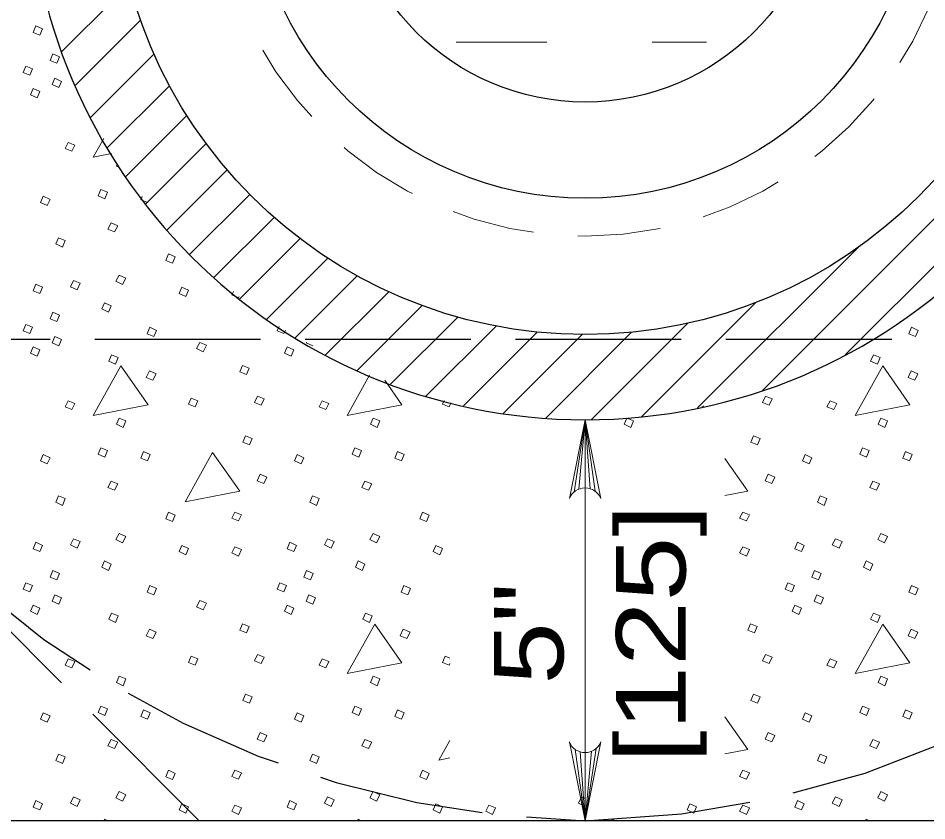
# Model space of a CAD drawing. Extents: x 1036.7 to 1070.7, y 883.9 to 905.9.
# Drawn here: x 1046.559 to 1048.598, y 887.577 to 889.378 of the extents above; entities that cross this region are included whole.
import ezdxf
from ezdxf.enums import TextEntityAlignment as Align

# ---------------------------------------------------------------- set-up
doc = ezdxf.new("R2010")
doc.units = 0
doc.header["$LTSCALE"] = 0.062
doc.linetypes.add('LONG_DASHED', pattern=[7.5, 6, -1.5])
doc.linetypes.add('MEDIUM_DASHED', pattern=[4.5, 3, -1.5])
doc.layers.add('1', color=7, linetype='Continuous', lineweight=13)

msp = doc.modelspace()

# ---------------------------------------------------------------- linework, layer by layer
at = {"layer": '1'}
for p, q in [((1046.65633, 889.30225), (1046.80892, 889.45483)), ((1046.68667, 889.22658), (1046.83392, 889.37383)), ((1047.542, 889.32425), (1047.74533, 889.32425)), ((1047.98175, 889.32425), (1048.10333, 889.32425)), ((1048.22892, 888.5425), (1049.01425, 889.32775)), ((1046.72092, 889.15475), (1046.864, 889.29783)), ((1046.75892, 889.08675), (1046.89883, 889.22658)), ((1046.80025, 889.02208), (1046.93783, 889.15958)), ((1048.41458, 888.62217), (1048.93458, 889.14208)), ((1046.84492, 888.96075), (1046.98092, 889.09675)), ((1046.89283, 888.90267), (1047.02792, 889.03775)), ((1046.94383, 888.84767), (1047.07875, 888.9825)), ((1046.998, 888.79583), (1047.13325, 888.93108)), ((1047.05533, 888.74708), (1047.19158, 888.88333)), ((1048.08367, 888.50333), (1048.44467, 888.86417)), ((1047.11625, 888.70208), (1047.25383, 888.83958)), ((1047.18058, 888.66033), (1047.32, 888.79983)), ((1047.24825, 888.622), (1047.3905, 888.76425)), ((1047.3195, 888.58725), (1047.46558, 888.73325)), ((1047.958, 888.48358), (1048.21417, 888.73983)), ((1047.39467, 888.55642), (1047.54558, 888.70733)), ((1047.474, 888.52975), (1047.63142, 888.68708)), ((1047.84558, 888.47733), (1048.06175, 888.69342)), ((1047.55808, 888.50783), (1047.72383, 888.6735)), ((1047.64742, 888.49117), (1047.82433, 888.668)), ((1047.74292, 888.48067), (1047.9355, 888.67317)), ((1047.80642, 888.31467), (1047.83117, 888.47683)), ((1047.81683, 888.32083), (1047.83117, 888.47683)), ((1047.83117, 888.47683), (1047.83117, 887.88908)), ((1047.83117, 888.32367), (1047.83117, 888.47683)), ((1047.8425, 888.322), (1047.83117, 888.47683)), ((1047.85358, 888.31658), (1047.83117, 888.47683)), ((1047.51725, 887.94592), (1047.528, 887.94167)), ((1047.83117, 887.57667), (1047.83117, 887.88908)), ((1047.80875, 887.73692), (1047.83117, 887.57667)), ((1047.81983, 887.7315), (1047.83117, 887.57667)), ((1047.856, 887.73883), (1047.83117, 887.57667)), ((1047.84558, 887.73267), (1047.83117, 887.57667)), ((1047.83117, 887.72983), (1047.83117, 887.57667)), ((1047.82308, 887.63017), (1047.83117, 887.62692)), ((1046.75117, 887.57667), (1046.75267, 887.58017)), ((1046.75267, 887.58017), (1046.76008, 887.57667)), ((1047.32083, 887.57667), (1047.32233, 887.58017)), ((1047.32233, 887.58017), (1047.32983, 887.57667)), ((1047.89058, 887.57667), (1047.89208, 887.58017)), ((1047.89208, 887.58017), (1047.89958, 887.57667)), ((1048.46033, 887.57667), (1048.46183, 887.58017)), ((1048.46183, 887.58017), (1048.46933, 887.57667))]:
    msp.add_line(p, q, dxfattribs=at)
at = {"layer": '1', "linetype": 'LONG_DASHED', "lineweight": 25}
for p, q in [((1045.72733, 888.81858), (1046.9655, 887.57667)), ((1049.935, 888.65658), (1046.35942, 888.65658))]:
    msp.add_line(p, q, dxfattribs=at)
at = {"layer": '1', "lineweight": 25}
for points in [[(1045.72733, 891.87417), (1049.935, 891.87417), (1049.935, 887.57667), (1047.83117, 887.57667)], [(1047.83117, 887.57667), (1045.72733, 887.57667), (1045.72733, 891.87417)]]:
    msp.add_lwpolyline(points, dxfattribs=at)
at = {"layer": '1'}
for points in [[(1046.59867, 889.36117), (1046.61367, 889.35417), (1046.60767, 889.34017), (1046.59267, 889.34617)], [(1046.63667, 889.29817), (1046.65167, 889.29117), (1046.64567, 889.27717), (1046.63067, 889.28317)], [(1046.57675, 889.27017), (1046.59167, 889.26417), (1046.58567, 889.25017), (1046.57075, 889.25617)], [(1046.64167, 889.24317), (1046.65667, 889.23625), (1046.65067, 889.22225), (1046.63567, 889.22925)], [(1046.59267, 889.22025), (1046.60767, 889.21325), (1046.60167, 889.19925), (1046.58667, 889.20625)], [(1046.67167, 889.09925), (1046.68667, 889.09325), (1046.67967, 889.07933), (1046.66467, 889.08533)], [(1046.74467, 888.99333), (1046.75958, 888.98733), (1046.75367, 888.97233), (1046.73867, 888.97933)], [(1046.61567, 888.97833), (1046.63067, 888.97133), (1046.62467, 888.95733), (1046.60967, 888.96433)], [(1046.76758, 888.91842), (1046.78258, 888.91242), (1046.77558, 888.89842), (1046.76058, 888.90442)], [(1046.64967, 888.88542), (1046.66467, 888.87942), (1046.65867, 888.86442), (1046.64367, 888.87142)], [(1046.89658, 888.84942), (1046.91158, 888.84242), (1046.90558, 888.82842), (1046.89058, 888.83442)], [(1046.68367, 888.7895), (1046.69867, 888.7835), (1046.69167, 888.7685), (1046.67667, 888.7755)], [(1046.78558, 888.80142), (1046.80058, 888.7945), (1046.79358, 888.7805), (1046.77858, 888.7875)], [(1046.59867, 888.7815), (1046.61367, 888.7745), (1046.60767, 888.7605), (1046.59267, 888.7665)], [(1046.92658, 888.7745), (1046.9415, 888.7675), (1046.93558, 888.7535), (1046.92058, 888.7605)], [(1046.75267, 888.7395), (1046.76758, 888.7325), (1046.76158, 888.7185), (1046.74667, 888.7255)], [(1046.63667, 888.7185), (1046.65167, 888.7115), (1046.64567, 888.6975), (1046.63067, 888.7035)], [(1046.57675, 888.6905), (1046.59167, 888.6845), (1046.58567, 888.6705), (1046.57075, 888.6765)], [(1046.85458, 888.6845), (1046.86958, 888.6775), (1046.86358, 888.6635), (1046.84858, 888.6695)], [(1048.56375, 888.6845), (1048.57875, 888.6775), (1048.57275, 888.6635), (1048.55775, 888.6695)], [(1046.64167, 888.6635), (1046.65667, 888.65658), (1046.65067, 888.64258), (1046.63567, 888.64958)], [(1046.59267, 888.64058), (1046.60767, 888.63358), (1046.60167, 888.61958), (1046.58667, 888.62658)], [(1046.9665, 888.65058), (1046.9815, 888.64458), (1046.9745, 888.62958), (1046.9595, 888.63658)], [(1047.16242, 888.64058), (1047.17742, 888.63358), (1047.17142, 888.61958), (1047.15642, 888.62658)], [(1046.76858, 888.62258), (1046.78358, 888.61658), (1046.77758, 888.60158), (1046.76258, 888.60858)], [(1048.47783, 888.62258), (1048.49283, 888.61658), (1048.48683, 888.60158), (1048.47183, 888.60858)], [(1046.78958, 888.59758), (1046.72767, 888.48667), (1046.85058, 888.51067)], [(1046.85358, 888.58658), (1046.86858, 888.57958), (1046.86158, 888.56558), (1046.84658, 888.57158)], [(1047.0625, 888.59858), (1047.0775, 888.59258), (1047.0715, 888.57858), (1047.0565, 888.58458)], [(1048.49883, 888.59758), (1048.43683, 888.48667), (1048.55975, 888.51067)], [(1048.56275, 888.58658), (1048.57775, 888.57958), (1048.57075, 888.56558), (1048.55575, 888.57158)], [(1046.67167, 888.51958), (1046.68667, 888.51358), (1046.67967, 888.49967), (1046.66467, 888.50567)], [(1046.9475, 888.52558), (1046.9625, 888.51958), (1046.9565, 888.50567), (1046.9415, 888.51167)], [(1047.0965, 888.52958), (1047.1115, 888.52358), (1047.1045, 888.50967), (1047.0895, 888.51558)], [(1047.24142, 888.51958), (1047.25642, 888.51358), (1047.24942, 888.49967), (1047.23442, 888.50567)], [(1048.23592, 888.52958), (1048.25092, 888.52358), (1048.24392, 888.50967), (1048.22892, 888.51558)], [(1048.38083, 888.51958), (1048.39583, 888.51358), (1048.38883, 888.49967), (1048.37383, 888.50567)], [(1046.78558, 888.48067), (1046.80058, 888.47467), (1046.79458, 888.45967), (1046.77958, 888.46667)], [(1047.35533, 888.48067), (1047.37033, 888.47467), (1047.36433, 888.45967), (1047.34933, 888.46667)], [(1047.92508, 888.48067), (1047.94008, 888.47467), (1047.93408, 888.45967), (1047.91908, 888.46667)], [(1048.49483, 888.48067), (1048.50983, 888.47467), (1048.50383, 888.45967), (1048.48883, 888.46667)], [(1047.0695, 888.44067), (1047.0845, 888.43467), (1047.0785, 888.42067), (1047.0635, 888.42667)], [(1048.20892, 888.44067), (1048.22392, 888.43467), (1048.21792, 888.42067), (1048.20292, 888.42667)], [(1046.61567, 888.39867), (1046.63067, 888.39167), (1046.62467, 888.37767), (1046.60967, 888.38467)], [(1046.74467, 888.41367), (1046.75958, 888.40767), (1046.75367, 888.39267), (1046.73867, 888.39967)], [(1046.84058, 888.40567), (1046.85558, 888.39867), (1046.84958, 888.38467), (1046.83458, 888.39067)], [(1046.9955, 888.40367), (1046.93358, 888.29275), (1047.0565, 888.31675)], [(1047.18542, 888.39867), (1047.20042, 888.39167), (1047.19442, 888.37767), (1047.17942, 888.38467)], [(1047.31433, 888.41367), (1047.32933, 888.40767), (1047.32333, 888.39267), (1047.30833, 888.39967)], [(1047.41033, 888.40567), (1047.42533, 888.39867), (1047.41933, 888.38467), (1047.40433, 888.39067)], [(1048.32492, 888.39867), (1048.33992, 888.39167), (1048.33392, 888.37767), (1048.31892, 888.38467)], [(1048.45383, 888.41367), (1048.46883, 888.40767), (1048.46283, 888.39267), (1048.44783, 888.39967)], [(1048.54975, 888.40567), (1048.56475, 888.39867), (1048.55875, 888.38467), (1048.54375, 888.39067)], [(1047.1025, 888.35475), (1047.11742, 888.34775), (1047.11042, 888.33375), (1047.0955, 888.33975)], [(1048.24192, 888.35475), (1048.25692, 888.34775), (1048.24992, 888.33375), (1048.23492, 888.33975)], [(1046.76758, 888.33875), (1046.78258, 888.33275), (1046.77558, 888.31875), (1046.76058, 888.32475)], [(1047.33733, 888.33875), (1047.35233, 888.33275), (1047.34533, 888.31875), (1047.33033, 888.32475)], [(1048.47683, 888.33875), (1048.49183, 888.33275), (1048.48483, 888.31875), (1048.46983, 888.32475)], [(1046.64967, 888.30575), (1046.66467, 888.29975), (1046.65867, 888.28475), (1046.64367, 888.29175)], [(1047.21942, 888.30575), (1047.23442, 888.29975), (1047.22842, 888.28475), (1047.21342, 888.29175)], [(1048.35883, 888.30575), (1048.37383, 888.29975), (1048.36783, 888.28475), (1048.35292, 888.29175)], [(1046.89658, 888.26975), (1046.91158, 888.26275), (1046.90558, 888.24875), (1046.89058, 888.25475)], [(1047.0455, 888.26975), (1047.0605, 888.26375), (1047.0535, 888.24975), (1047.0385, 888.25575)], [(1047.46625, 888.26975), (1047.48125, 888.26275), (1047.47525, 888.24875), (1047.46033, 888.25475)], [(1048.18492, 888.26975), (1048.19992, 888.26375), (1048.19292, 888.24975), (1048.17792, 888.25575)], [(1046.78558, 888.22175), (1046.80058, 888.21483), (1046.79358, 888.20083), (1046.77858, 888.20783)], [(1047.35533, 888.22175), (1047.37033, 888.21483), (1047.36333, 888.20083), (1047.34833, 888.20783)], [(1048.49483, 888.22175), (1048.50983, 888.21483), (1048.50283, 888.20083), (1048.48783, 888.20783)], [(1046.59867, 888.20183), (1046.61367, 888.19483), (1046.60767, 888.18083), (1046.59267, 888.18683)], [(1046.68367, 888.20983), (1046.69867, 888.20383), (1046.69167, 888.18883), (1046.67667, 888.19583)], [(1046.92658, 888.19483), (1046.9415, 888.18783), (1046.93558, 888.17383), (1046.92058, 888.18083)], [(1047.0455, 888.19183), (1047.0605, 888.18583), (1047.0535, 888.17083), (1047.0385, 888.17783)], [(1047.16842, 888.20183), (1047.18342, 888.19483), (1047.17742, 888.18083), (1047.16242, 888.18683)], [(1047.25342, 888.20983), (1047.26842, 888.20383), (1047.26142, 888.18883), (1047.24642, 888.19583)], [(1047.49625, 888.19483), (1047.51125, 888.18783), (1047.50525, 888.17383), (1047.49025, 888.18083)], [(1048.18492, 888.19183), (1048.19992, 888.18583), (1048.19292, 888.17083), (1048.17792, 888.17783)], [(1048.30792, 888.20183), (1048.32292, 888.19483), (1048.31692, 888.18083), (1048.30192, 888.18683)], [(1048.39283, 888.20983), (1048.40783, 888.20383), (1048.40083, 888.18883), (1048.38583, 888.19583)], [(1046.75267, 888.15983), (1046.76758, 888.15283), (1046.76158, 888.13883), (1046.74667, 888.14583)], [(1047.32233, 888.15983), (1047.33733, 888.15283), (1047.33133, 888.13883), (1047.31633, 888.14583)], [(1048.46183, 888.15983), (1048.47683, 888.15283), (1048.47083, 888.13883), (1048.45583, 888.14583)], [(1046.63667, 888.13883), (1046.65167, 888.13183), (1046.64567, 888.11783), (1046.63067, 888.12383)], [(1047.20642, 888.13883), (1047.22142, 888.13183), (1047.21542, 888.11783), (1047.20042, 888.12383)], [(1048.34592, 888.13883), (1048.36083, 888.13183), (1048.35483, 888.11783), (1048.33992, 888.12383)], [(1046.57675, 888.11083), (1046.59167, 888.10483), (1046.58567, 888.09083), (1046.57075, 888.09683)], [(1047.14642, 888.11083), (1047.16142, 888.10483), (1047.15542, 888.09083), (1047.14042, 888.09683)], [(1048.28592, 888.11083), (1048.30092, 888.10483), (1048.29492, 888.09083), (1048.27992, 888.09683)], [(1046.85458, 888.10483), (1046.86958, 888.09783), (1046.86358, 888.08383), (1046.84858, 888.08983)], [(1047.42433, 888.10483), (1047.43933, 888.09783), (1047.43333, 888.08383), (1047.41833, 888.08983)], [(1048.56375, 888.10483), (1048.57875, 888.09783), (1048.57275, 888.08383), (1048.55775, 888.08983)], [(1046.64167, 888.08383), (1046.65667, 888.07683), (1046.65067, 888.06292), (1046.63567, 888.06992)], [(1046.9665, 888.07092), (1046.9815, 888.06492), (1046.9745, 888.04992), (1046.9595, 888.05692)], [(1047.21142, 888.08383), (1047.22642, 888.07683), (1047.22042, 888.06292), (1047.20542, 888.06992)], [(1048.35083, 888.08383), (1048.36583, 888.07683), (1048.35983, 888.06292), (1048.34492, 888.06992)], [(1046.59267, 888.06092), (1046.60767, 888.05392), (1046.60167, 888.03992), (1046.58667, 888.04692)], [(1047.16242, 888.06092), (1047.17742, 888.05392), (1047.17142, 888.03992), (1047.15642, 888.04692)], [(1048.30192, 888.06092), (1048.31692, 888.05392), (1048.31092, 888.03992), (1048.29592, 888.04692)], [(1046.76858, 888.04292), (1046.78358, 888.03692), (1046.77758, 888.02192), (1046.76258, 888.02892)], [(1047.33833, 888.04292), (1047.35333, 888.03692), (1047.34733, 888.02192), (1047.33233, 888.02892)], [(1048.47783, 888.04292), (1048.49283, 888.03692), (1048.48683, 888.02192), (1048.47183, 888.02892)], [(1047.0625, 888.01892), (1047.0775, 888.01292), (1047.0715, 887.99892), (1047.0565, 888.00492)], [(1047.35933, 888.01792), (1047.29733, 887.907), (1047.42033, 887.931)], [(1048.20192, 888.01892), (1048.21692, 888.01292), (1048.21092, 887.99892), (1048.19592, 888.00492)], [(1048.49883, 888.01792), (1048.43683, 887.907), (1048.55975, 887.931)], [(1046.85358, 888.00692), (1046.86858, 887.99992), (1046.86158, 887.98592), (1046.84658, 887.99192)], [(1047.42333, 888.00692), (1047.43833, 887.99992), (1047.43133, 887.98592), (1047.41633, 887.99192)], [(1048.56275, 888.00692), (1048.57775, 887.99992), (1048.57075, 887.98592), (1048.55575, 887.99192)], [(1047.0965, 887.94992), (1047.1115, 887.94392), (1047.1045, 887.93), (1047.0895, 887.93592)], [(1048.23592, 887.94992), (1048.25092, 887.94392), (1048.24392, 887.93), (1048.22892, 887.93592)], [(1046.67167, 887.93992), (1046.68667, 887.93392), (1046.67967, 887.92), (1046.66467, 887.926)], [(1046.9475, 887.94592), (1046.9625, 887.93992), (1046.9565, 887.926), (1046.9415, 887.932)], [(1047.24142, 887.93992), (1047.25642, 887.93392), (1047.24942, 887.92), (1047.23442, 887.926)], [(1048.38083, 887.93992), (1048.39583, 887.93392), (1048.38883, 887.92), (1048.37383, 887.926)], [(1046.78558, 887.901), (1046.80058, 887.895), (1046.79458, 887.88), (1046.77958, 887.887)], [(1047.35533, 887.901), (1047.37033, 887.895), (1047.36433, 887.88), (1047.34933, 887.887)], [(1048.49483, 887.901), (1048.50983, 887.895), (1048.50383, 887.88), (1048.48883, 887.887)], [(1047.0695, 887.861), (1047.0845, 887.855), (1047.0785, 887.841), (1047.0635, 887.847)], [(1048.20892, 887.861), (1048.22392, 887.855), (1048.21792, 887.841), (1048.20292, 887.847)], [(1046.74467, 887.834), (1046.75958, 887.828), (1046.75367, 887.813), (1046.73867, 887.82)], [(1046.84058, 887.826), (1046.85558, 887.819), (1046.84958, 887.805), (1046.83458, 887.811)], [(1047.31433, 887.834), (1047.32933, 887.828), (1047.32333, 887.813), (1047.30833, 887.82)], [(1047.41033, 887.826), (1047.42533, 887.819), (1047.41933, 887.805), (1047.40433, 887.811)], [(1048.45383, 887.834), (1048.46883, 887.828), (1048.46283, 887.813), (1048.44783, 887.82)], [(1048.54975, 887.826), (1048.56475, 887.819), (1048.55875, 887.805), (1048.54375, 887.811)], [(1046.61567, 887.819), (1046.63067, 887.812), (1046.62467, 887.798), (1046.60967, 887.805)], [(1047.18542, 887.819), (1047.20042, 887.812), (1047.19442, 887.798), (1047.17942, 887.805)], [(1048.32492, 887.819), (1048.33992, 887.812), (1048.33392, 887.798), (1048.31892, 887.805)], [(1047.1025, 887.77508), (1047.11742, 887.76808), (1047.11042, 887.75408), (1047.0955, 887.76008)], [(1048.24192, 887.77508), (1048.25692, 887.76808), (1048.24992, 887.75408), (1048.23492, 887.76008)], [(1046.76758, 887.75908), (1046.78258, 887.75308), (1046.77558, 887.73908), (1046.76058, 887.74508)], [(1047.33733, 887.75908), (1047.35233, 887.75308), (1047.34533, 887.73908), (1047.33033, 887.74508)], [(1048.47683, 887.75908), (1048.49183, 887.75308), (1048.48483, 887.73908), (1048.46983, 887.74508)], [(1046.64967, 887.72608), (1046.66467, 887.72008), (1046.65867, 887.70508), (1046.64367, 887.71208)], [(1047.21942, 887.72608), (1047.23442, 887.72008), (1047.22842, 887.70508), (1047.21342, 887.71208)], [(1048.35883, 887.72608), (1048.37383, 887.72008), (1048.36783, 887.70508), (1048.35292, 887.71208)], [(1046.89658, 887.69008), (1046.91158, 887.68308), (1046.90558, 887.66908), (1046.89058, 887.67508)], [(1047.0455, 887.69008), (1047.0605, 887.68408), (1047.0535, 887.67008), (1047.0385, 887.67608)], [(1047.46625, 887.69008), (1047.48125, 887.68308), (1047.47525, 887.66908), (1047.46033, 887.67508)], [(1048.18492, 887.69008), (1048.19992, 887.68408), (1048.19292, 887.67008), (1048.17792, 887.67608)], [(1046.78558, 887.64217), (1046.80058, 887.63517), (1046.79358, 887.62117), (1046.77858, 887.62817)], [(1047.35533, 887.64217), (1047.37033, 887.63517), (1047.36333, 887.62117), (1047.34833, 887.62817)], [(1048.49483, 887.64217), (1048.50983, 887.63517), (1048.50283, 887.62117), (1048.48783, 887.62817)], [(1046.59867, 887.62217), (1046.61367, 887.61517), (1046.60767, 887.60117), (1046.59267, 887.60717)], [(1046.68367, 887.63017), (1046.69867, 887.62417), (1046.69167, 887.60917), (1046.67667, 887.61617)], [(1047.16842, 887.62217), (1047.18342, 887.61517), (1047.17742, 887.60117), (1047.16242, 887.60717)], [(1047.25342, 887.63017), (1047.26842, 887.62417), (1047.26142, 887.60917), (1047.24642, 887.61617)], [(1048.30792, 887.62217), (1048.32292, 887.61517), (1048.31692, 887.60117), (1048.30192, 887.60717)], [(1048.39283, 887.63017), (1048.40783, 887.62417), (1048.40083, 887.60917), (1048.38583, 887.61617)], [(1046.92658, 887.61517), (1046.9415, 887.60817), (1046.93558, 887.59417), (1046.92058, 887.60117)], [(1047.0455, 887.61217), (1047.0605, 887.60617), (1047.0535, 887.59117), (1047.0385, 887.59817)], [(1047.49625, 887.61517), (1047.51125, 887.60817), (1047.50525, 887.59417), (1047.49025, 887.60117)], [(1047.61525, 887.61217), (1047.63025, 887.60617), (1047.62325, 887.59117), (1047.60825, 887.59817)], [(1048.066, 887.61517), (1048.081, 887.60817), (1048.075, 887.59417), (1048.06, 887.60117)], [(1048.18492, 887.61217), (1048.19992, 887.60617), (1048.19292, 887.59117), (1048.17792, 887.59817)]]:
    msp.add_lwpolyline(points, close=True, dxfattribs=at)
for points in [[(1046.75108, 889.10817), (1046.72767, 889.06633), (1046.76858, 889.07433)], [(1046.78583, 889.04342), (1046.77958, 889.04633), (1046.78117, 889.05)], [(1046.84775, 888.96508), (1046.83458, 888.97033), (1046.83758, 888.97792)], [(1047.05492, 888.75358), (1047.0535, 888.7505), (1047.0385, 888.7575), (1047.04208, 888.76467)], [(1047.15867, 888.67817), (1047.15542, 888.6705), (1047.14042, 888.6765), (1047.14458, 888.68617)], [(1047.2205, 888.64283), (1047.22042, 888.64258), (1047.20542, 888.64958), (1047.20608, 888.65108)], [(1047.34783, 888.577), (1047.29733, 888.48667), (1047.42033, 888.51067), (1047.38192, 888.56542)], [(1047.53025, 888.51483), (1047.52625, 888.50567), (1047.51125, 888.51167), (1047.51492, 888.52008)], [(1048.097, 888.508), (1048.096, 888.50567), (1048.09308, 888.50683)], [(1047.79583, 888.29983), (1047.83117, 888.47683), (1047.86658, 888.29983)], [(1048.14475, 888.30675), (1048.19592, 888.31675), (1048.14475, 888.38975)], [(1047.528, 887.92992), (1047.52625, 887.926), (1047.51125, 887.932), (1047.51725, 887.94592)], [(1048.14475, 887.72708), (1048.19592, 887.73708), (1048.14475, 887.81008)], [(1047.528, 887.75725), (1047.50325, 887.71308), (1047.528, 887.71792)], [(1047.86658, 887.75367), (1047.83117, 887.57667), (1047.79583, 887.75367)], [(1047.83117, 887.60933), (1047.83108, 887.60917), (1047.81617, 887.61617), (1047.82308, 887.63017)]]:
    msp.add_lwpolyline(points, dxfattribs=at)
for centre, start, end in [((1047.83124, 888.28551), 22.08782, 157.91395), ((1047.83116, 887.76796), 202.08782, 337.91395)]:
    msp.add_arc(centre, 0.0382, start, end, dxfattribs=at)
at = {"layer": '1', "linetype": 'LONG_DASHED', "lineweight": 25}
for centre, major_axis, start_param, end_param in [((1047.78549, 889.72543), (2.14947, 0), 4.7336585, 7.8327121), ((1047.87683, 889.72543), (-2.14947, 0), 0.1702167, 1.5495663)]:
    msp.add_ellipse(centre, major_axis=major_axis, ratio=0.999895, start_param=start_param, end_param=end_param, dxfattribs=at)
at = {"layer": '1', "lineweight": 25}
for start_param, end_param in [(4.712389, 7.8539816), (3.1415927, 4.712389)]:
    msp.add_ellipse((1047.8312, 889.72543), major_axis=(1.24875, 0), ratio=0.999895, start_param=start_param, end_param=end_param, dxfattribs=at)
for major_axis in [(1.05751, 0), (0.75159, 0), (0.53563, 0)]:
    msp.add_ellipse((1047.8312, 889.72543), major_axis=major_axis, ratio=0.999895, dxfattribs=at)
at = {"layer": '1', "linetype": 'MEDIUM_DASHED'}
msp.add_ellipse((1047.8312, 889.72543), major_axis=(0.83646, 0), ratio=0.999895, dxfattribs=at)

# ---------------------------------------------------------------- texts
at = {"layer": '1'}
for s, width, p in [('[125]', 1.25, (1048.05658, 887.99683)), ('5"', 1.2, (1047.78258, 887.99687))]:
    msp.add_text(s, height=0.156, rotation=90, dxfattribs=dict(at, width=width)).set_placement(p, align=Align.CENTER)

doc.saveas('drawing.dxf')
